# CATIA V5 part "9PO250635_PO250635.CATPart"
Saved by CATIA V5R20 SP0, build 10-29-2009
Part number: 9PO250635_PO250635
Revision: ANY
Definition: UNKNOWN
Nomenclature: 9PO250635_PO250635
Source: Unknown
Bounding box of the stored display mesh (mm): x -5.85 to 5.85, y 0 to 24.5, z -6 to 6
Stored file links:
  C:\Users\Utente\Desktop\IO LAVORO\3D X SITO CF\CUMSA\3D files PO\PO 250635\9PO250635_PO250635.CATPart
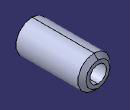
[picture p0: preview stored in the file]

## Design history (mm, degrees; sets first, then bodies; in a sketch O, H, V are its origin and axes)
Body1 "Chaflán2" (main body)
  Solid1: solid without history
